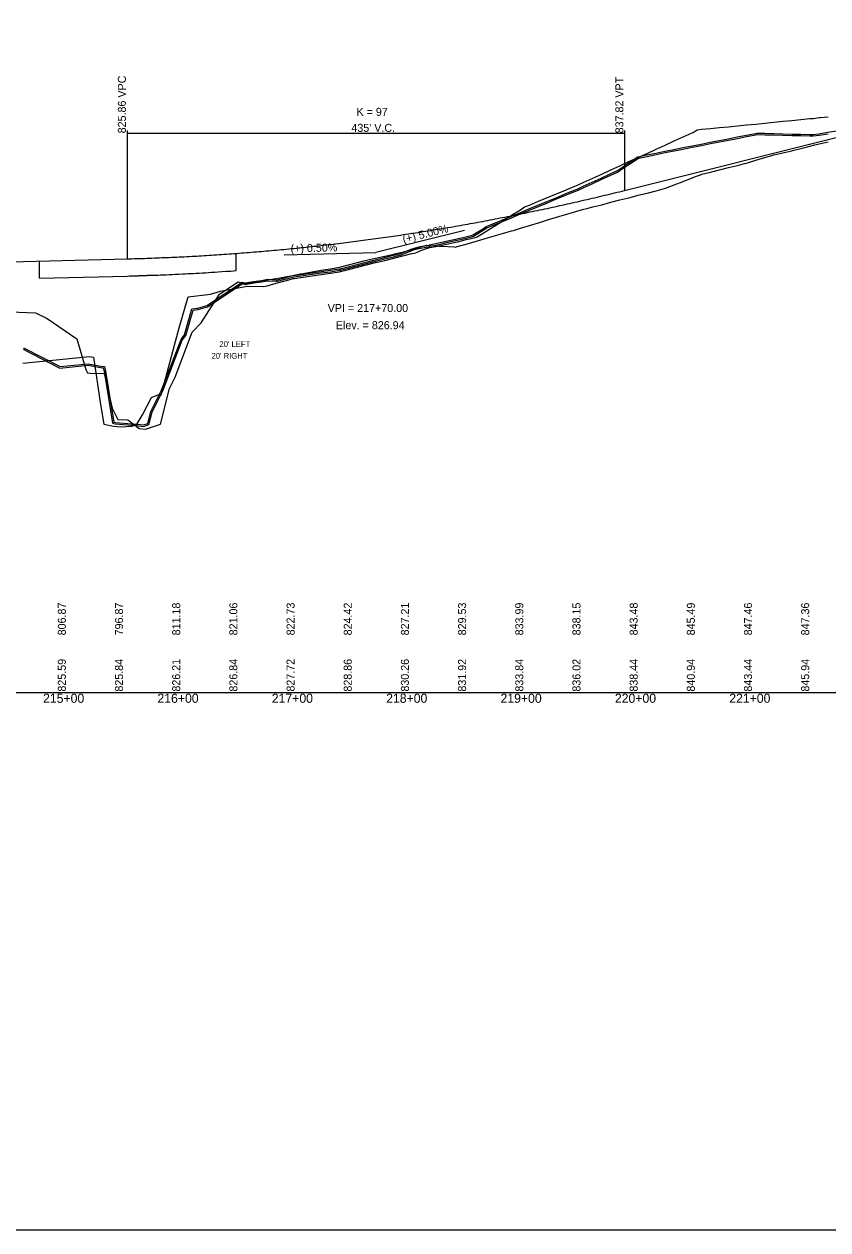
# Model space of a CAD drawing. Extents: x 1475855 to 1480900, y 1104511 to 1111511.
# Drawn here: x 1478626 to 1479329, y 1105041 to 1106096 of the extents above; entities that cross this region are included whole.
import ezdxf

# ---------------------------------------------------------------- set-up
doc = ezdxf.new("R2010")
doc.units = 0
for name, color, linetype in [('Default', 7, 'Continuous'), ('RD_DDB_GradeTX', 7, 'Continuous'), ('RD_DDB_Profile_EX', 7, 'Continuous'), ('RD_DDB_Profile_Lbl', 7, 'Continuous'), ('RD_DDB_Profile_PR', 7, 'Continuous'), ('RD_DDB_StaTX', 7, 'Continuous'), ('RD_DDB_StripGrade', 7, 'Continuous'), ('RD_DDB_VCLbl', 7, 'Continuous'), ('RD_GPK_Profile_Cell', 7, 'Continuous'), ('RD_PD_Bridge', 7, 'Continuous'), ('RD_Sketch2', 7, 'Continuous'), ('RD_Sketch3', 7, 'Continuous'), ('RD_Sketch7', 7, 'Continuous'), ('RD_Sketch8', 7, 'Continuous')]:
    doc.layers.add(name, color=color, linetype=linetype)

msp = doc.modelspace()

# ---------------------------------------------------------------- linework, layer by layer
at = {"layer": 'Default'}
for p, q in [((1478811.5, 1105880.2), (1478811.5, 1105895.3)), ((1478639.5, 1105873.6), (1478639.5, 1105888.6))]:
    msp.add_line(p, q, dxfattribs=at)
at = {"layer": 'RD_DDB_GradeTX'}
for p in [(1479011.1, 1105915.4), (1478853.5, 1105894)]:
    msp.add_line(p, (1478933.5, 1105896), dxfattribs=at)
at = {"layer": 'RD_DDB_Profile_EX'}
msp.add_lwpolyline([(1478625.2, 1105811.6), (1478657.2, 1105795), (1478682, 1105797.5), (1478694.7, 1105795.2), (1478695.2, 1105795.2), (1478695.9, 1105792.2), (1478703.3, 1105746.8), (1478705.6, 1105746.3), (1478720.3, 1105745), (1478721.4, 1105745.1), (1478730.6, 1105743.9), (1478735.2, 1105745.5), (1478738, 1105756.7), (1478747.4, 1105775.2), (1478764.3, 1105819.3), (1478767.3, 1105823.4), (1478773.7, 1105845.6), (1478778.1, 1105846.2), (1478786.3, 1105848.6), (1478816.8, 1105868.8), (1478818.6, 1105868.3), (1478819.4, 1105868.1), (1478826.8, 1105869.4), (1478833.7, 1105870.4), (1478838.4, 1105871.2), (1478838.9, 1105871.3), (1478846.4, 1105871), (1478847.5, 1105871), (1478854.3, 1105872.8), (1478859.9, 1105874.3), (1478862.2, 1105874.7), (1478868.3, 1105875.6), (1478870.1, 1105875.9), (1478878, 1105877), (1478885.9, 1105878.2), (1478893.8, 1105879.3), (1478901.7, 1105880.5), (1478902.8, 1105880.6), (1478909.7, 1105882.4), (1478917.6, 1105884.4), (1478925.5, 1105886.4), (1478933.4, 1105888.4), (1478941.3, 1105890.4), (1478949.2, 1105892.4), (1478952.2, 1105893.2), (1478955, 1105893.8), (1478957.1, 1105894.7), (1478965, 1105897.9), (1478967.3, 1105898.8), (1478973, 1105899.9), (1478980.5, 1105901.4), (1478980.9, 1105901.5), (1478988.8, 1105903.2), (1478996.7, 1105905), (1479003.3, 1105906.5), (1479004.6, 1105906.8), (1479012.5, 1105908.7), (1479017.1, 1105909.8), (1479018.9, 1105910.3), (1479020.4, 1105911.2), (1479028.3, 1105916.2), (1479030.7, 1105917.7), (1479036.3, 1105920), (1479044.2, 1105923.2), (1479052.1, 1105926.5), (1479060, 1105929.8), (1479067.9, 1105933), (1479075.8, 1105936.3), (1479083.7, 1105939.6), (1479091.6, 1105942.9), (1479099.5, 1105946.1), (1479107.5, 1105949.4), (1479110, 1105950.4), (1479115.4, 1105952.9), (1479123.3, 1105956.5), (1479131.2, 1105960.1), (1479139.1, 1105963.7), (1479145, 1105966.4), (1479147, 1105967.8), (1479154.9, 1105973.1), (1479163.1, 1105978.6), (1479170.8, 1105980.1), (1479178.7, 1105981.8), (1479186.6, 1105983.4), (1479194.5, 1105985), (1479202.4, 1105986.5), (1479210.3, 1105988.1), (1479213.6, 1105988.7), (1479218.2, 1105989.7), (1479226.1, 1105991.3), (1479234.1, 1105992.8), (1479242, 1105994.4), (1479249.9, 1105995.9), (1479257.8, 1105997.5), (1479265.7, 1105999), (1479266.8, 1105999.2), (1479273.6, 1105999), (1479281.5, 1105998.9), (1479289.4, 1105998.7), (1479297.3, 1105998.5), (1479305.3, 1105998.3), (1479313.2, 1105998.1), (1479316, 1105998), (1479321.1, 1105998.8), (1479329, 1106000)], dxfattribs=at)
at = {"layer": 'RD_DDB_Profile_PR'}
for p, q in [((1479151, 1105950.3), (1479438.5, 1106022.2)), ((1478436, 1105883.5), (1478716, 1105890.5))]:
    msp.add_line(p, q, dxfattribs=at)
msp.add_spline([(1478716, 1105890.5), (1478724.7, 1105890.8), (1478733.4, 1105891), (1478742.1, 1105891.4), (1478750.8, 1105891.7), (1478759.5, 1105892.1), (1478768.2, 1105892.5), (1478776.9, 1105893), (1478785.6, 1105893.5), (1478794.3, 1105894.1), (1478803, 1105894.7), (1478811.7, 1105895.3), (1478820.4, 1105896), (1478829.1, 1105896.7), (1478837.8, 1105897.4), (1478846.5, 1105898.2), (1478855.2, 1105899), (1478863.9, 1105899.9), (1478872.6, 1105900.8), (1478881.3, 1105901.7), (1478890, 1105902.7), (1478898.7, 1105903.7), (1478907.4, 1105904.8), (1478916.1, 1105905.9), (1478924.8, 1105907), (1478933.5, 1105908.2), (1478942.2, 1105909.4), (1478950.9, 1105910.7), (1478959.6, 1105912), (1478968.3, 1105913.3), (1478977, 1105914.7), (1478985.7, 1105916.1), (1478994.4, 1105917.5), (1479003.1, 1105919), (1479011.8, 1105920.6), (1479020.5, 1105922.1), (1479029.2, 1105923.7), (1479037.9, 1105925.4), (1479046.6, 1105927.1), (1479055.3, 1105928.8), (1479064, 1105930.6), (1479072.7, 1105932.4), (1479081.4, 1105934.2), (1479090.1, 1105936.1), (1479098.8, 1105938), (1479107.5, 1105940), (1479116.2, 1105942), (1479124.9, 1105944), (1479133.6, 1105946.1), (1479142.3, 1105948.2), (1479151, 1105950.3)], degree=3, dxfattribs=at)
at = {"layer": 'RD_DDB_VCLbl'}
for p, q in [((1478716, 1106002.8), (1478716, 1105890.5)), ((1478716, 1106000.3), (1479151, 1106000.3)), ((1479151, 1106002.8), (1479151, 1105950.3))]:
    msp.add_line(p, q, dxfattribs=at)
at = {"layer": 'RD_GPK_Profile_Cell'}
msp.add_line((1477363.5, 1105511.2), (1479982.4, 1105511.2), dxfattribs=at)
at = {"layer": 'RD_PD_Bridge'}
for p, q in [((1478811.5, 1105880.2), (1478811.5, 1105895.3)), ((1478639.5, 1105873.6), (1478639.5, 1105888.6)), ((1478639.5, 1105873.6), (1478716.3, 1105875.5))]:
    msp.add_line(p, q, dxfattribs=at)
msp.add_open_spline([(1478716.4, 1105875.5), (1478718.7, 1105875.6), (1478721.5, 1105875.7), (1478724.4, 1105875.8), (1478725, 1105875.8), (1478725.1, 1105875.8), (1478725.1, 1105875.8), (1478725.1, 1105875.8), (1478725.1, 1105875.8), (1478725.1, 1105875.8), (1478725.2, 1105875.8), (1478725.5, 1105875.8), (1478726, 1105875.8), (1478726.4, 1105875.8), (1478727.9, 1105875.9), (1478729.1, 1105875.9), (1478731.4, 1105876), (1478732.5, 1105876), (1478733.7, 1105876.1), (1478733.8, 1105876.1), (1478733.9, 1105876.1), (1478733.9, 1105876.1), (1478733.9, 1105876.1), (1478734, 1105876.1), (1478734.2, 1105876.1), (1478734.7, 1105876.1), (1478735.7, 1105876.1), (1478738.9, 1105876.2), (1478741.7, 1105876.3), (1478753.3, 1105876.8), (1478762.5, 1105877.2), (1478785, 1105878.4), (1478798.2, 1105879.3), (1478811.5, 1105880.2)], degree=3, dxfattribs=at)
at = {"layer": 'RD_Sketch2'}
msp.add_lwpolyline([(1478584.8, 1105845.2), (1478635.9, 1105843.4), (1478646.1, 1105838.4), (1478672, 1105820.6), (1478680.1, 1105793.8), (1478681.4, 1105790.7), (1478683.9, 1105790.4), (1478696.1, 1105790.1), (1478703.1, 1105759.8), (1478708.1, 1105749.9), (1478716.7, 1105749.6), (1478726.7, 1105742.1), (1478732.3, 1105741.4), (1478745.2, 1105745.9), (1478753.1, 1105777.2), (1478758, 1105787.1), (1478773.1, 1105826.3), (1478780.7, 1105834.6), (1478796.9, 1105859.6), (1478813.1, 1105870.3), (1478817, 1105869.3), (1478818.7, 1105868.8), (1478834.7, 1105871.7), (1478838.4, 1105872.3), (1478846.4, 1105873.4), (1478849.7, 1105873.9), (1478854.3, 1105874.7), (1478856.1, 1105875), (1478862.2, 1105876.3), (1478867.5, 1105877.3), (1478870.1, 1105877.8), (1478878, 1105879.2), (1478885.9, 1105880.6), (1478893.8, 1105881.9), (1478901.7, 1105883.3), (1478902.9, 1105883.5), (1478909.7, 1105885.3), (1478917.6, 1105887.4), (1478923.1, 1105888.8), (1478925.5, 1105889.3), (1478933.4, 1105891.1), (1478941.3, 1105892.9), (1478949.2, 1105894.7), (1478951.1, 1105895.1), (1478955, 1105896), (1478957.1, 1105896.5), (1478958.7, 1105896.8), (1478962.6, 1105897.9), (1478965, 1105898.4), (1478965.5, 1105898.5), (1478973, 1105900.9), (1478977.8, 1105902.5), (1478980.9, 1105902.3), (1478988.8, 1105901.7), (1478996.7, 1105901.2), (1479002.4, 1105900.9), (1479003.3, 1105900.8), (1479004.6, 1105901.2), (1479012.5, 1105903.5), (1479020.4, 1105905.8), (1479028.3, 1105908), (1479036.3, 1105910.3), (1479044.2, 1105912.6), (1479052.1, 1105914.9), (1479053.8, 1105915.4), (1479060, 1105917.3), (1479067.9, 1105919.7), (1479075.8, 1105922.1), (1479083.7, 1105924.5), (1479091.6, 1105926.9), (1479099.5, 1105929.3), (1479107.5, 1105931.7), (1479110.2, 1105932.6), (1479115.4, 1105933.9), (1479118.1, 1105934.6), (1479123.3, 1105935.9), (1479131.2, 1105937.9), (1479139.1, 1105940), (1479147, 1105942), (1479154.9, 1105944), (1479162, 1105945.8), (1479162.8, 1105946.1), (1479170.8, 1105948.1), (1479178.7, 1105950.1), (1479186.8, 1105952.2), (1479194.5, 1105955.2), (1479202.4, 1105958.2), (1479210.3, 1105961.3), (1479213.9, 1105962.7), (1479217.5, 1105964.1), (1479218.5, 1105964.5), (1479226.1, 1105966.4), (1479234.1, 1105968.3), (1479242, 1105970.3), (1479249.9, 1105972.3), (1479256, 1105973.8), (1479257.8, 1105974.3), (1479265.7, 1105976.7), (1479273.6, 1105979.2), (1479279.7, 1105981), (1479281.5, 1105981.4), (1479289.4, 1105983.2), (1479297.3, 1105985), (1479297.9, 1105985.2), (1479305.3, 1105987.1), (1479311, 1105988.5), (1479313.2, 1105989.1), (1479317.4, 1105990.2), (1479321.1, 1105991.1), (1479329, 1105993)], dxfattribs=at)
at = {"layer": 'RD_Sketch3'}
msp.add_lwpolyline([(1478625, 1105799.3), (1478683.3, 1105805.1), (1478686.8, 1105804.5), (1478692.8, 1105763.1), (1478695.6, 1105745.9), (1478704.2, 1105744.1), (1478710.6, 1105743.5), (1478719.9, 1105744.2), (1478724.2, 1105745.2), (1478729.5, 1105754), (1478737.5, 1105769.1), (1478743.7, 1105771.9), (1478746, 1105771.6), (1478761.7, 1105830.1), (1478769.4, 1105857.2), (1478788.9, 1105859.7), (1478797.7, 1105862.3), (1478821, 1105866.7), (1478835.2, 1105866.2), (1478838.4, 1105867), (1478846.4, 1105869.2), (1478854.3, 1105871.3), (1478861.6, 1105873.3), (1478862.2, 1105873.4), (1478870.1, 1105874.6), (1478878, 1105875.8), (1478879.5, 1105876), (1478885.9, 1105876.9), (1478893.8, 1105878.1), (1478901.7, 1105879.2), (1478902.8, 1105879.4), (1478909.7, 1105881.1), (1478917.6, 1105883.1), (1478925.5, 1105885.2), (1478933.4, 1105887.2), (1478936.1, 1105887.9), (1478941.3, 1105889.1), (1478949.2, 1105891.1), (1478957.1, 1105893.1), (1478965, 1105895.1), (1478968.5, 1105895.9), (1478973, 1105897.7), (1478977.9, 1105899.7), (1478980.9, 1105900.3), (1478987.9, 1105901.7), (1478988.8, 1105901.9), (1478996.7, 1105903.6), (1479004.6, 1105905.4), (1479005.2, 1105905.5), (1479012.5, 1105907.3), (1479015.7, 1105908.1), (1479020.4, 1105909.3), (1479022.1, 1105909.7), (1479028.3, 1105913.6), (1479036.3, 1105918.6), (1479044.2, 1105923.6), (1479052.1, 1105928.6), (1479060, 1105933.5), (1479063.7, 1105935.9), (1479067.9, 1105937.6), (1479075.8, 1105940.9), (1479083.7, 1105944.2), (1479091.6, 1105947.4), (1479099.5, 1105950.7), (1479107.5, 1105954), (1479110.5, 1105955.2), (1479115.4, 1105957.5), (1479123.3, 1105961.1), (1479131.2, 1105964.7), (1479139.1, 1105968.3), (1479147, 1105972), (1479154.9, 1105975.6), (1479162.8, 1105979.2), (1479170.8, 1105982.8), (1479178.7, 1105986.4), (1479186.6, 1105990), (1479194.5, 1105993.6), (1479202.4, 1105997.2), (1479210.3, 1106000.8), (1479211, 1106001.1), (1479214.4, 1106003.4), (1479218.2, 1106003.8), (1479226.1, 1106004.5), (1479234.1, 1106005.3), (1479242, 1106006.1), (1479249.9, 1106006.9), (1479257.8, 1106007.7), (1479265.7, 1106008.4), (1479273.6, 1106009.2), (1479281.5, 1106010), (1479289.4, 1106010.8), (1479297.3, 1106011.6), (1479305.3, 1106012.4), (1479313.2, 1106013.2), (1479313.8, 1106013.3), (1479315.2, 1106013.3), (1479316.3, 1106013.4), (1479321.1, 1106014.1), (1479322.1, 1106014.2), (1479329, 1106014.8)], dxfattribs=at)
at = {"layer": 'RD_Sketch7'}
msp.add_lwpolyline([(1477173.9, 1105041.2), (1480053.9, 1105041.2), (1480053.9, 1106801.2), (1477173.9, 1106801.2)], close=True, dxfattribs=at)
at = {"layer": 'RD_Sketch8'}
msp.add_lwpolyline([(1478625.6, 1105812.8), (1478657.4, 1105796.3), (1478682, 1105798.7), (1478694.9, 1105796.4), (1478696.2, 1105796.4), (1478697.1, 1105792.4), (1478704.4, 1105747.8), (1478705.8, 1105747.5), (1478720.3, 1105746.2), (1478721.4, 1105746.3), (1478730.5, 1105745.2), (1478734.2, 1105746.5), (1478736.8, 1105757.1), (1478746.2, 1105775.7), (1478763.2, 1105819.9), (1478766.2, 1105824), (1478772.7, 1105846.8), (1478777.8, 1105847.4), (1478785.8, 1105849.8), (1478816.6, 1105870.1), (1478818.9, 1105869.5), (1478819.5, 1105869.4), (1478826.6, 1105870.7), (1478833.5, 1105871.7), (1478838.8, 1105872.6), (1478846.4, 1105872.3), (1478847.3, 1105872.3), (1478853.9, 1105874), (1478859.6, 1105875.6), (1478862, 1105875.9), (1478868.1, 1105876.8), (1478869.9, 1105877.1), (1478877.8, 1105878.3), (1478885.7, 1105879.4), (1478893.7, 1105880.6), (1478901.6, 1105881.7), (1478902.6, 1105881.8), (1478909.3, 1105883.6), (1478917.3, 1105885.6), (1478925.2, 1105887.6), (1478933.1, 1105889.6), (1478941, 1105891.6), (1478948.9, 1105893.6), (1478951.9, 1105894.4), (1478954.6, 1105895), (1478956.7, 1105895.9), (1478964.6, 1105899.1), (1478967, 1105900), (1478972.7, 1105901.2), (1478980.3, 1105902.6), (1478980.6, 1105902.7), (1478988.5, 1105904.4), (1478996.4, 1105906.2), (1479003.1, 1105907.7), (1479004.3, 1105908), (1479012.2, 1105909.9), (1479016.8, 1105911), (1479018.4, 1105911.4), (1479019.8, 1105912.3), (1479027.7, 1105917.2), (1479030.1, 1105918.8), (1479035.8, 1105921.1), (1479043.7, 1105924.4), (1479051.6, 1105927.7), (1479059.5, 1105930.9), (1479067.4, 1105934.2), (1479075.3, 1105937.5), (1479083.2, 1105940.7), (1479091.2, 1105944), (1479099.1, 1105947.3), (1479107, 1105950.5), (1479109.5, 1105951.6), (1479114.9, 1105954), (1479122.8, 1105957.6), (1479130.7, 1105961.2), (1479138.6, 1105964.8), (1479144.4, 1105967.5), (1479146.3, 1105968.8), (1479154.2, 1105974.1), (1479162.6, 1105979.8), (1479170.5, 1105981.4), (1479178.4, 1105983), (1479186.3, 1105984.6), (1479194.2, 1105986.2), (1479202.2, 1105987.8), (1479210.1, 1105989.3), (1479213.4, 1105990), (1479218, 1105990.9), (1479225.9, 1105992.5), (1479233.8, 1105994.1), (1479241.7, 1105995.6), (1479249.6, 1105997.2), (1479257.6, 1105998.7), (1479265.5, 1106000.2), (1479266.7, 1106000.4), (1479273.6, 1106000.3), (1479281.6, 1106000.1), (1479289.5, 1105999.9), (1479297.4, 1105999.7), (1479305.3, 1105999.5), (1479313.2, 1105999.3), (1479315.9, 1105999.2), (1479320.9, 1106000), (1479328.8, 1106001.2), (1479336.7, 1106002.4)], dxfattribs=at)

# ---------------------------------------------------------------- texts
at = {"layer": 'RD_DDB_GradeTX'}
for s, rotation, p in [('(+) 5.00%', 14.0362, (1478957.9, 1105904.1)), ('(+) 0.50%', 1.4321, (1478859.1, 1105896.1))]:
    msp.add_text(s, height=7, rotation=rotation, dxfattribs=at).set_placement(p)
at = {"layer": 'RD_DDB_Profile_Lbl'}
for s, p in [('VPI = 217+70.00', (1478891.5, 1105844)), ('Elev. = 826.94', (1478898.6, 1105829))]:
    msp.add_text(s, height=7, dxfattribs=at).set_placement(p)
at = {"layer": 'RD_DDB_StaTX'}
for s, p in [('215+00', (1478642.6, 1105502.2)), ('216+00', (1478742.6, 1105502.2)), ('217+00', (1478842.6, 1105502.2)), ('218+00', (1478942.6, 1105502.2)), ('219+00', (1479042.6, 1105502.2)), ('220+00', (1479142.6, 1105502.2)), ('221+00', (1479242.6, 1105502.2))]:
    msp.add_text(s, height=8, dxfattribs=at).set_placement(p)
at = {"layer": 'RD_DDB_StripGrade'}
for s, p in [('825.86 VPC', (1478715, 1106000.3)), ('837.82 VPT', (1479150, 1106000.3)), ('806.87', (1478662.5, 1105561.2)), ('796.87', (1478712.5, 1105561.2)), ('811.18', (1478762.5, 1105561.2)), ('821.06', (1478812.5, 1105561.2)), ('822.73', (1478862.5, 1105561.2)), ('824.42', (1478912.5, 1105561.2)), ('827.21', (1478962.5, 1105561.2)), ('829.53', (1479012.5, 1105561.2)), ('833.99', (1479062.5, 1105561.2)), ('838.15', (1479112.5, 1105561.2)), ('843.48', (1479162.5, 1105561.2)), ('845.49', (1479212.5, 1105561.2)), ('847.46', (1479262.5, 1105561.2)), ('847.36', (1479312.5, 1105561.2)), ('825.59', (1478662.5, 1105512)), ('825.84', (1478712.5, 1105512)), ('826.21', (1478762.5, 1105512)), ('826.84', (1478812.5, 1105512)), ('827.72', (1478862.5, 1105512)), ('828.86', (1478912.5, 1105512)), ('830.26', (1478962.5, 1105512)), ('831.92', (1479012.5, 1105512)), ('833.84', (1479062.5, 1105512)), ('836.02', (1479112.5, 1105512)), ('838.44', (1479162.5, 1105512)), ('840.94', (1479212.5, 1105512)), ('843.44', (1479262.5, 1105512)), ('845.94', (1479312.5, 1105512))]:
    msp.add_text(s, height=7, rotation=90, dxfattribs=at).set_placement(p)
at = {"layer": 'RD_DDB_VCLbl'}
for s, p in [('K = 97', (1478916.7, 1106015.6)), ("435' V.C.", (1478912.2, 1106001.6))]:
    msp.add_text(s, height=7, dxfattribs=at).set_placement(p)
at = {"layer": 'RD_Sketch2'}
msp.add_text("20' LEFT", height=5, dxfattribs=at).set_placement((1478796.8, 1105813.5))
at = {"layer": 'RD_Sketch3'}
msp.add_text("20' RIGHT", height=5, dxfattribs=at).set_placement((1478789.9, 1105803.2))

doc.saveas('drawing.dxf')
